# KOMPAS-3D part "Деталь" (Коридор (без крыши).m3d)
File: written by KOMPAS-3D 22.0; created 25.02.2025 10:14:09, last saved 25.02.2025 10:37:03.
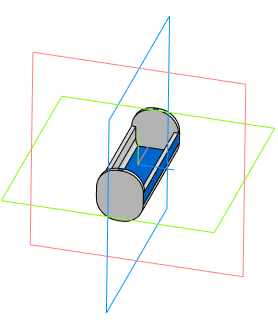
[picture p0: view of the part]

Document properties: Автор: Пользователь Windows; Полное имя файла: C:\Users\Student\Documents\Картошечка\База Сабнатика\Коридор\Коридор (без крыши).m3d

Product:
- Body: Тело 1
    Масса: 0.008372
- Part/product: Деталь
    Масса: 0.009492

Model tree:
1. Эскиз:1
2. Элемент выдавливания:1
     Расстояние 1 = 30
3. Эскиз:2  (with: Элемент выдавливания:1)
4. Элемент выдавливания:2
     Расстояние 2 = 5
5. Оболочка:1  (with: Элемент выдавливания:2)
     Толщина стенки 2 = 1
6. Эскиз:3  (with: Оболочка:1)
7. Элемент выдавливания:3
     Расстояние 1 = 28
